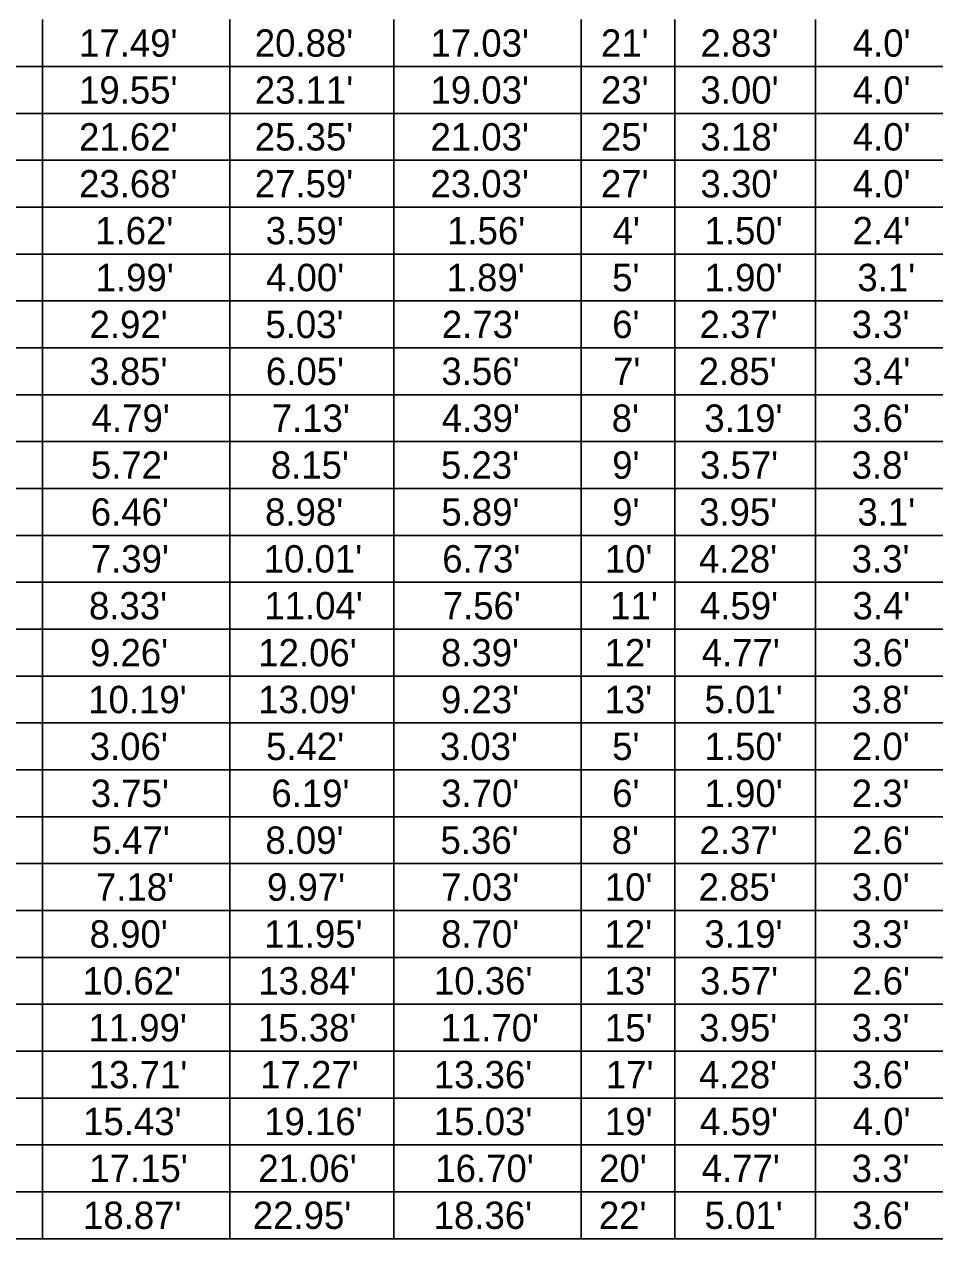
# Model space of a CAD drawing. Extents: x 1.7 to 14.6, y 0 to 8.4.
# Drawn here: x 3.994 to 6.325, y 2.19 to 5.298 of the extents above; entities that cross this region are included whole.
import ezdxf

# ---------------------------------------------------------------- set-up
doc = ezdxf.new("R2010")
doc.units = 0
doc.layers.add('Table', color=7, linetype='Continuous')

msp = doc.modelspace()

# ---------------------------------------------------------------- linework, layer by layer
at = {"layer": 'Table'}
for points in [[(4.04, 5.31), (4.04, 5.19), (4.04, 5.07), (4.04, 4.95), (4.04, 4.83), (4.04, 4.71), (4.04, 4.59), (4.04, 4.47), (4.04, 4.35), (4.04, 4.23), (4.04, 4.11), (4.04, 3.99), (4.04, 3.87), (4.04, 3.75), (4.04, 3.63), (4.04, 3.51), (4.04, 3.39), (4.04, 3.27), (4.04, 3.15), (4.04, 3.03), (4.04, 2.91), (4.04, 2.79), (4.04, 2.67), (4.04, 2.55), (4.04, 2.43), (4.04, 2.31), (4.04, 2.19)], [(4.52, 5.31), (4.52, 5.19), (4.52, 5.07), (4.52, 4.95), (4.52, 4.83), (4.52, 4.71), (4.52, 4.59), (4.52, 4.47), (4.52, 4.35), (4.52, 4.23), (4.52, 4.11), (4.52, 3.99), (4.52, 3.87), (4.52, 3.75), (4.52, 3.63), (4.52, 3.51), (4.52, 3.39), (4.52, 3.27), (4.52, 3.15), (4.52, 3.03), (4.52, 2.91), (4.52, 2.79), (4.52, 2.67), (4.52, 2.55), (4.52, 2.43), (4.52, 2.31), (4.52, 2.19)], [(4.94, 5.31), (4.94, 5.19), (4.94, 5.07), (4.94, 4.95), (4.94, 4.83), (4.94, 4.71), (4.94, 4.59), (4.94, 4.47), (4.94, 4.35), (4.94, 4.23), (4.94, 4.11), (4.94, 3.99), (4.94, 3.87), (4.94, 3.75), (4.94, 3.63), (4.94, 3.51), (4.94, 3.39), (4.94, 3.27), (4.94, 3.15), (4.94, 3.03), (4.94, 2.91), (4.94, 2.79), (4.94, 2.67), (4.94, 2.55), (4.94, 2.43), (4.94, 2.31), (4.94, 2.19)], [(5.42, 5.31), (5.42, 5.19), (5.42, 5.07), (5.42, 4.95), (5.42, 4.83), (5.42, 4.71), (5.42, 4.59), (5.42, 4.47), (5.42, 4.35), (5.42, 4.23), (5.42, 4.11), (5.42, 3.99), (5.42, 3.87), (5.42, 3.75), (5.42, 3.63), (5.42, 3.51), (5.42, 3.39), (5.42, 3.27), (5.42, 3.15), (5.42, 3.03), (5.42, 2.91), (5.42, 2.79), (5.42, 2.67), (5.42, 2.55), (5.42, 2.43), (5.42, 2.31), (5.42, 2.19)], [(5.66, 5.31), (5.66, 5.19), (5.66, 5.07), (5.66, 4.95), (5.66, 4.83), (5.66, 4.71), (5.66, 4.59), (5.66, 4.47), (5.66, 4.35), (5.66, 4.23), (5.66, 4.11), (5.66, 3.99), (5.66, 3.87), (5.66, 3.75), (5.66, 3.63), (5.66, 3.51), (5.66, 3.39), (5.66, 3.27), (5.66, 3.15), (5.66, 3.03), (5.66, 2.91), (5.66, 2.79), (5.66, 2.67), (5.66, 2.55), (5.66, 2.43), (5.66, 2.31), (5.66, 2.19)], [(6.02, 5.31), (6.02, 5.19), (6.02, 5.07), (6.02, 4.95), (6.02, 4.83), (6.02, 4.71), (6.02, 4.59), (6.02, 4.47), (6.02, 4.35), (6.02, 4.23), (6.02, 4.11), (6.02, 3.99), (6.02, 3.87), (6.02, 3.75), (6.02, 3.63), (6.02, 3.51), (6.02, 3.39), (6.02, 3.27), (6.02, 3.15), (6.02, 3.03), (6.02, 2.91), (6.02, 2.79), (6.02, 2.67), (6.02, 2.55), (6.02, 2.43), (6.02, 2.31), (6.02, 2.19)], [(2.3, 5.19), (2.6, 5.19), (2.9, 5.19), (3.2, 5.19), (3.62, 5.19), (4.04, 5.19), (4.52, 5.19), (4.94, 5.19), (5.42, 5.19), (5.66, 5.19), (6.02, 5.19), (6.38, 5.19)], [(2.3, 5.07), (2.6, 5.07), (2.9, 5.07), (3.2, 5.07), (3.62, 5.07), (4.04, 5.07), (4.52, 5.07), (4.94, 5.07), (5.42, 5.07), (5.66, 5.07), (6.02, 5.07), (6.38, 5.07)], [(2.3, 4.95), (2.6, 4.95), (2.9, 4.95), (3.2, 4.95), (3.62, 4.95), (4.04, 4.95), (4.52, 4.95), (4.94, 4.95), (5.42, 4.95), (5.66, 4.95), (6.02, 4.95), (6.38, 4.95)], [(1.7, 4.83), (1.94, 4.83), (2.3, 4.83), (2.6, 4.83), (2.9, 4.83), (3.2, 4.83), (3.62, 4.83), (4.04, 4.83), (4.52, 4.83), (4.94, 4.83), (5.42, 4.83), (5.66, 4.83), (6.02, 4.83), (6.38, 4.83)], [(2.3, 4.71), (2.6, 4.71), (2.9, 4.71), (3.2, 4.71), (3.62, 4.71), (4.04, 4.71), (4.52, 4.71), (4.94, 4.71), (5.42, 4.71), (5.66, 4.71), (6.02, 4.71), (6.38, 4.71)], [(2.3, 4.59), (2.6, 4.59), (2.9, 4.59), (3.2, 4.59), (3.62, 4.59), (4.04, 4.59), (4.52, 4.59), (4.94, 4.59), (5.42, 4.59), (5.66, 4.59), (6.02, 4.59), (6.38, 4.59)], [(2.3, 4.47), (2.6, 4.47), (2.9, 4.47), (3.2, 4.47), (3.62, 4.47), (4.04, 4.47), (4.52, 4.47), (4.94, 4.47), (5.42, 4.47), (5.66, 4.47), (6.02, 4.47), (6.38, 4.47)], [(2.3, 4.35), (2.6, 4.35), (2.9, 4.35), (3.2, 4.35), (3.62, 4.35), (4.04, 4.35), (4.52, 4.35), (4.94, 4.35), (5.42, 4.35), (5.66, 4.35), (6.02, 4.35), (6.38, 4.35)], [(2.3, 4.23), (2.6, 4.23), (2.9, 4.23), (3.2, 4.23), (3.62, 4.23), (4.04, 4.23), (4.52, 4.23), (4.94, 4.23), (5.42, 4.23), (5.66, 4.23), (6.02, 4.23), (6.38, 4.23)], [(2.3, 4.11), (2.6, 4.11), (2.9, 4.11), (3.2, 4.11), (3.62, 4.11), (4.04, 4.11), (4.52, 4.11), (4.94, 4.11), (5.42, 4.11), (5.66, 4.11), (6.02, 4.11), (6.38, 4.11)], [(2.3, 3.99), (2.6, 3.99), (2.9, 3.99), (3.2, 3.99), (3.62, 3.99), (4.04, 3.99), (4.52, 3.99), (4.94, 3.99), (5.42, 3.99), (5.66, 3.99), (6.02, 3.99), (6.38, 3.99)], [(2.3, 3.87), (2.6, 3.87), (2.9, 3.87), (3.2, 3.87), (3.62, 3.87), (4.04, 3.87), (4.52, 3.87), (4.94, 3.87), (5.42, 3.87), (5.66, 3.87), (6.02, 3.87), (6.38, 3.87)], [(2.3, 3.75), (2.6, 3.75), (2.9, 3.75), (3.2, 3.75), (3.62, 3.75), (4.04, 3.75), (4.52, 3.75), (4.94, 3.75), (5.42, 3.75), (5.66, 3.75), (6.02, 3.75), (6.38, 3.75)], [(2.3, 3.63), (2.6, 3.63), (2.9, 3.63), (3.2, 3.63), (3.62, 3.63), (4.04, 3.63), (4.52, 3.63), (4.94, 3.63), (5.42, 3.63), (5.66, 3.63), (6.02, 3.63), (6.38, 3.63)], [(1.94, 3.51), (2.3, 3.51), (2.6, 3.51), (2.9, 3.51), (3.2, 3.51), (3.62, 3.51), (4.04, 3.51), (4.52, 3.51), (4.94, 3.51), (5.42, 3.51), (5.66, 3.51), (6.02, 3.51), (6.38, 3.51)], [(2.3, 3.39), (2.6, 3.39), (2.9, 3.39), (3.2, 3.39), (3.62, 3.39), (4.04, 3.39), (4.52, 3.39), (4.94, 3.39), (5.42, 3.39), (5.66, 3.39), (6.02, 3.39), (6.38, 3.39)], [(2.3, 3.27), (2.6, 3.27), (2.9, 3.27), (3.2, 3.27), (3.62, 3.27), (4.04, 3.27), (4.52, 3.27), (4.94, 3.27), (5.42, 3.27), (5.66, 3.27), (6.02, 3.27), (6.38, 3.27)], [(2.3, 3.15), (2.6, 3.15), (2.9, 3.15), (3.2, 3.15), (3.62, 3.15), (4.04, 3.15), (4.52, 3.15), (4.94, 3.15), (5.42, 3.15), (5.66, 3.15), (6.02, 3.15), (6.38, 3.15)], [(2.3, 3.03), (2.6, 3.03), (2.9, 3.03), (3.2, 3.03), (3.62, 3.03), (4.04, 3.03), (4.52, 3.03), (4.94, 3.03), (5.42, 3.03), (5.66, 3.03), (6.02, 3.03), (6.38, 3.03)], [(2.3, 2.91), (2.6, 2.91), (2.9, 2.91), (3.2, 2.91), (3.62, 2.91), (4.04, 2.91), (4.52, 2.91), (4.94, 2.91), (5.42, 2.91), (5.66, 2.91), (6.02, 2.91), (6.38, 2.91)], [(2.3, 2.79), (2.6, 2.79), (2.9, 2.79), (3.2, 2.79), (3.62, 2.79), (4.04, 2.79), (4.52, 2.79), (4.94, 2.79), (5.42, 2.79), (5.66, 2.79), (6.02, 2.79), (6.38, 2.79)], [(2.3, 2.67), (2.6, 2.67), (2.9, 2.67), (3.2, 2.67), (3.62, 2.67), (4.04, 2.67), (4.52, 2.67), (4.94, 2.67), (5.42, 2.67), (5.66, 2.67), (6.02, 2.67), (6.38, 2.67)], [(2.3, 2.55), (2.6, 2.55), (2.9, 2.55), (3.2, 2.55), (3.62, 2.55), (4.04, 2.55), (4.52, 2.55), (4.94, 2.55), (5.42, 2.55), (5.66, 2.55), (6.02, 2.55), (6.38, 2.55)], [(2.3, 2.43), (2.6, 2.43), (2.9, 2.43), (3.2, 2.43), (3.62, 2.43), (4.04, 2.43), (4.52, 2.43), (4.94, 2.43), (5.42, 2.43), (5.66, 2.43), (6.02, 2.43), (6.38, 2.43)], [(2.3, 2.31), (2.6, 2.31), (2.9, 2.31), (3.2, 2.31), (3.62, 2.31), (4.04, 2.31), (4.52, 2.31), (4.94, 2.31), (5.42, 2.31), (5.66, 2.31), (6.02, 2.31), (6.38, 2.31)], [(1.7, 2.19), (1.94, 2.19), (2.3, 2.19), (2.6, 2.19), (2.9, 2.19), (3.2, 2.19), (3.62, 2.19), (4.04, 2.19), (4.52, 2.19), (4.94, 2.19), (5.42, 2.19), (5.66, 2.19), (6.02, 2.19), (6.38, 2.19)]]:
    msp.add_lwpolyline(points, dxfattribs=at)

# ---------------------------------------------------------------- texts
for s, p in [("17.49'", (4.134, 5.215)), ("20.88'", (4.584, 5.215)), ("17.03'", (5.034, 5.215)), ("21'", (5.4706, 5.215)), ("2.83'", (5.7254, 5.215)), ("4.0'", (6.1153, 5.215)), ("19.55'", (4.134, 5.095)), ("23.11'", (4.584, 5.095)), ("19.03'", (5.034, 5.095)), ("23'", (5.4706, 5.095)), ("3.00'", (5.7254, 5.095)), ("4.0'", (6.1153, 5.095)), ("21.62'", (4.134, 4.975)), ("25.35'", (4.584, 4.975)), ("21.03'", (5.034, 4.975)), ("25'", (5.4706, 4.975)), ("3.18'", (5.7254, 4.975)), ("4.0'", (6.1153, 4.975)), ("23.68'", (4.134, 4.855)), ("27.59'", (4.584, 4.855)), ("23.03'", (5.034, 4.855)), ("27'", (5.4706, 4.855)), ("3.30'", (5.7254, 4.855)), ("4.0'", (6.1153, 4.855)), ("1.62'", (4.1754, 4.735)), ("3.59'", (4.6119, 4.735)), ("1.56'", (5.0765, 4.735)), ("4'", (5.5003, 4.735)), ("1.50'", (5.7359, 4.735)), ("2.4'", (6.1148, 4.735)), ("1.99'", (4.1765, 4.615)), ("4.00'", (4.6129, 4.615)), ("1.89'", (5.0752, 4.615)), ("5'", (5.4992, 4.615)), ("1.90'", (5.7359, 4.615)), ("3.1'", (6.1272, 4.615)), ("2.92'", (4.1609, 4.495)), ("5.03'", (4.6113, 4.495)), ("2.73'", (5.063, 4.495)), ("6'", (5.4993, 4.495)), ("2.37'", (5.723, 4.495)), ("3.3'", (6.1126, 4.495)), ("3.85'", (4.1605, 4.375)), ("6.05'", (4.6125, 4.375)), ("3.56'", (5.0619, 4.375)), ("7'", (5.5015, 4.375)), ("2.85'", (5.7206, 4.375)), ("3.4'", (6.1147, 4.375)), ("4.79'", (4.1663, 4.255)), ("7.13'", (4.6275, 4.255)), ("4.39'", (5.0629, 4.255)), ("8'", (5.498, 4.255)), ("3.19'", (5.7353, 4.255)), ("3.6'", (6.1137, 4.255)), ("5.72'", (4.1642, 4.135)), ("8.15'", (4.6251, 4.135)), ("5.23'", (5.0608, 4.135)), ("9'", (5.4993, 4.135)), ("3.57'", (5.7241, 4.135)), ("3.8'", (6.1124, 4.135)), ("6.46'", (4.164, 4.015)), ("8.98'", (4.6104, 4.015)), ("5.89'", (5.0617, 4.015)), ("9'", (5.4993, 4.015)), ("3.95'", (5.7219, 4.015)), ("3.1'", (6.1272, 4.015)), ("7.39'", (4.1641, 3.895)), ("10.01'", (4.6069, 3.895)), ("6.73'", (5.0641, 3.895)), ("10'", (5.4803, 3.895)), ("4.28'", (5.7216, 3.895)), ("3.3'", (6.1126, 3.895)), ("8.33'", (4.1594, 3.775)), ("11.04'", (4.6085, 3.775)), ("7.56'", (5.0653, 3.775)), ("11'", (5.4943, 3.775)), ("4.59'", (5.724, 3.775)), ("3.4'", (6.1147, 3.775)), ("9.26'", (4.162, 3.655)), ("12.06'", (4.593, 3.655)), ("8.39'", (5.0606, 3.655)), ("12'", (5.4797, 3.655)), ("4.77'", (5.7285, 3.655)), ("3.6'", (6.1137, 3.655)), ("10.19'", (4.1575, 3.535)), ("13.09'", (4.5929, 3.535)), ("9.23'", (5.0608, 3.535)), ("13'", (5.4797, 3.535)), ("5.01'", (5.7359, 3.535)), ("3.8'", (6.1124, 3.535)), ("3.06'", (4.1613, 3.415)), ("5.42'", (4.6129, 3.415)), (" 3.03'", (5.0319, 3.415)), ("5'", (5.4992, 3.415)), ("1.50'", (5.7359, 3.415)), ("2.0'", (6.1132, 3.415)), ("3.75'", (4.1641, 3.295)), ("6.19'", (4.6265, 3.295)), (" 3.70'", (5.0353, 3.295)), ("6'", (5.4993, 3.295)), ("1.90'", (5.7359, 3.295)), ("2.3'", (6.1126, 3.295)), ("5.47'", (4.1663, 3.175)), ("8.09'", (4.6112, 3.175)), (" 5.36'", (5.0336, 3.175)), ("8'", (5.498, 3.175)), ("2.37'", (5.723, 3.175)), ("2.6'", (6.1138, 3.175)), ("7.18'", (4.1774, 3.055)), ("9.97'", (4.6153, 3.055)), (" 7.03'", (5.0353, 3.055)), ("10'", (5.4803, 3.055)), ("2.85'", (5.7206, 3.055)), ("3.0'", (6.1132, 3.055)), ("8.90'", (4.1612, 2.935)), ("11.95'", (4.608, 2.935)), (" 8.70'", (5.0352, 2.935)), ("12'", (5.4797, 2.935)), ("3.19'", (5.7353, 2.935)), ("3.3'", (6.1126, 2.935)), ("10.62'", (4.143, 2.815)), ("13.84'", (4.5931, 2.815)), ("10.36'", (5.0429, 2.815)), ("13'", (5.4797, 2.815)), ("3.57'", (5.7241, 2.815)), ("2.6'", (6.1138, 2.815)), ("11.99'", (4.158, 2.695)), ("15.38'", (4.5921, 2.695)), ("11.70'", (5.0597, 2.695)), ("15'", (5.4808, 2.695)), ("3.95'", (5.7219, 2.695)), ("3.3'", (6.1126, 2.695)), ("13.71'", (4.1591, 2.575)), ("17.27'", (4.598, 2.575)), ("13.36'", (5.0423, 2.575)), ("17'", (5.4831, 2.575)), ("4.28'", (5.7216, 2.575)), ("3.6'", (6.1137, 2.575)), ("15.43'", (4.1444, 2.455)), ("19.16'", (4.608, 2.455)), ("15.03'", (5.0428, 2.455)), ("19'", (5.4808, 2.455)), ("4.59'", (5.724, 2.455)), ("4.0'", (6.1153, 2.455)), ("17.15'", (4.1603, 2.335)), ("21.06'", (4.593, 2.335)), ("16.70'", (5.0463, 2.335)), ("20'", (5.4658, 2.335)), ("4.77'", (5.7285, 2.335)), ("3.3'", (6.1126, 2.335)), ("18.87'", (4.1442, 2.215)), ("22.95'", (4.579, 2.215)), ("18.36'", (5.0421, 2.215)), ("22'", (5.4652, 2.215)), ("5.01'", (5.7359, 2.215)), ("3.6'", (6.1137, 2.215))]:
    msp.add_text(s, height=0.07, rotation=0, dxfattribs=at).set_placement(p)

doc.saveas('drawing.dxf')
